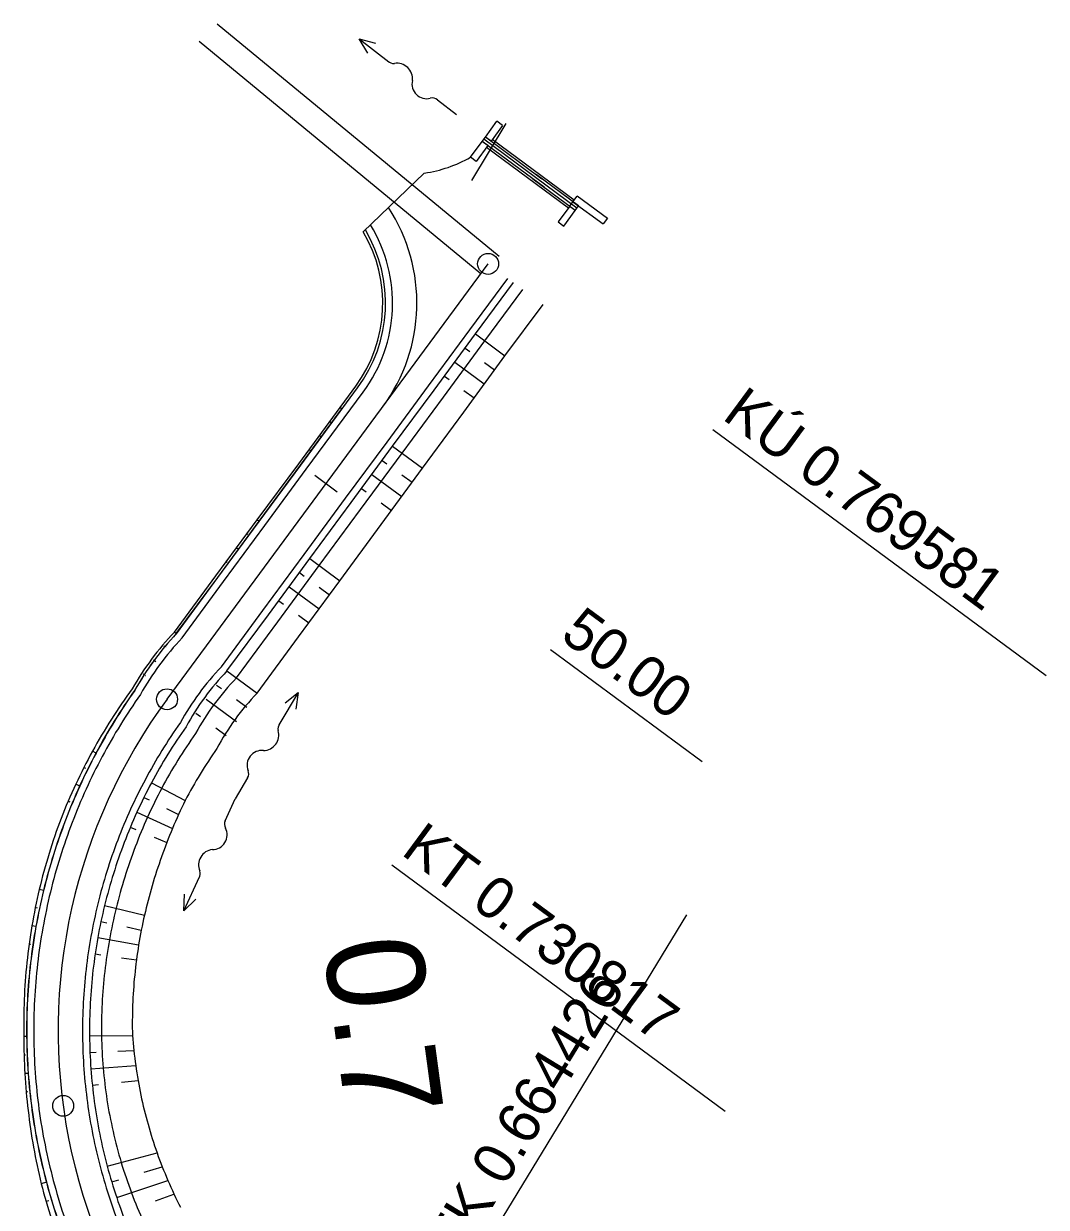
# Model space of a CAD drawing. Extents: x -481656 to -478728, y -1113199 to -1110710.
# Drawn here: x -479819.6 to -479746.4, y -1112732.9 to -1112648.1 of the extents above; entities that cross this region are included whole.
import ezdxf

# ---------------------------------------------------------------- set-up
doc = ezdxf.new("R2010")
doc.units = 0
for name, color, linetype in [('C1_HATCH_SLOPE_L', 7, 'Continuous'), ('C1_HATCH_SLOPE_R', 7, 'Continuous'), ('C1_HECTOMETRY', 7, 'Continuous'), ('C1_HLBODY', 7, 'Continuous'), ('C1_HRANA_TELESO', 7, 'Continuous'), ('C1_KORUNA', 7, 'Continuous'), ('C1_OSA', 7, 'Continuous'), ('C1_PRIKOP', 7, 'Continuous'), ('C1_STANICENI', 7, 'Continuous'), ('C1_VOZOVKA', 7, 'Continuous'), ('C1_ZPEVKRAJ', 7, 'Continuous'), ('DRENÁŽ', 7, 'Continuous'), ('křižovatky', 7, 'Continuous'), ('PLYN', 7, 'Continuous'), ('pomoc', 7, 'Continuous'), ('ŽLAB', 7, 'Continuous')]:
    doc.layers.add(name, color=color, linetype=linetype)

# ---------------------------------------------------------------- blocks, each defined once
blk = doc.blocks.new('A$C70B')
at = {"layer": 'DRENÁŽ'}
for p, q in [((0.869, 0.002), (-0.869, -0.002)), ((6.861, 0.426), (7.971, -0.002)), ((7.971, -0.002), (5.275, -0.002)), ((7.971, -0.002), (6.862, -0.478))]:
    blk.add_line(p, q, dxfattribs=at)
for centre, radius, start, end in [((0.872, 0.584), 0.582, 269.69241, 322.79009), ((2.168, -0.416), 1.055, 24.40393, 142.08362), ((4.08, 0.589), 1.109, 210.88731, 317.37071), ((5.319, -0.636), 0.636, 85.97658, 131.72478)]:
    blk.add_arc(centre, radius, start, end, dxfattribs=at)

msp = doc.modelspace()

# ---------------------------------------------------------------- linework, layer by layer
at = {"layer": 'C1_HATCH_SLOPE_L'}
for p, q in [((-479796.825, -1112675.729), (-479796.948, -1112675.638)), ((-479797.632, -1112676.686), (-479797.69, -1112676.644)), ((-479797.567, -1112676.735), (-479797.571, -1112676.732)), ((-479798.309, -1112677.741), (-479798.432, -1112677.65)), ((-479799.116, -1112678.698), (-479799.174, -1112678.656)), ((-479799.05, -1112678.747), (-479799.054, -1112678.744)), ((-479802.76, -1112683.778), (-479802.915, -1112683.663)), ((-479803.584, -1112684.724), (-479803.657, -1112684.669)), ((-479803.502, -1112684.784), (-479803.506, -1112684.781)), ((-479804.244, -1112685.79), (-479804.399, -1112685.675)), ((-479805.068, -1112686.736), (-479805.141, -1112686.681)), ((-479804.986, -1112686.796), (-479804.99, -1112686.793)), ((-479808.695, -1112691.826), (-479808.846, -1112691.715)), ((-479809.52, -1112692.771), (-479809.594, -1112692.716)), ((-479809.437, -1112692.832), (-479809.441, -1112692.829)), ((-479810.179, -1112693.838), (-479810.342, -1112693.717)), ((-479811.01, -1112694.778), (-479811.09, -1112694.719)), ((-479810.921, -1112694.844), (-479810.925, -1112694.841)), ((-479814.453, -1112700.385), (-479814.714, -1112700.245)), ((-479815.199, -1112701.488), (-479815.333, -1112701.422)), ((-479815.056, -1112701.559), (-479815.06, -1112701.557)), ((-479815.622, -1112702.752), (-479815.914, -1112702.619)), ((-479816.308, -1112703.896), (-479816.457, -1112703.833)), ((-479816.15, -1112703.962), (-479816.155, -1112703.96)), ((-479818.213, -1112710.226), (-479818.526, -1112710.149)), ((-479818.663, -1112711.48), (-479818.809, -1112711.449)), ((-479818.507, -1112711.513), (-479818.512, -1112711.512)), ((-479818.76, -1112712.808), (-479819.052, -1112712.756)), ((-479819.118, -1112714.09), (-479819.253, -1112714.07)), ((-479818.973, -1112714.111), (-479818.978, -1112714.11)), ((-479819.422, -1112720.691), (-479819.633, -1112720.693)), ((-479819.508, -1112722.016), (-479819.617, -1112722.02)), ((-479819.388, -1112722.011), (-479819.393, -1112722.011)), ((-479819.313, -1112723.329), (-479819.56, -1112723.347)), ((-479819.334, -1112724.658), (-479819.461, -1112724.672)), ((-479819.197, -1112724.644), (-479819.202, -1112724.644)), ((-479818.004, -1112731.13), (-479818.386, -1112731.232)), ((-479817.843, -1112732.46), (-479818.032, -1112732.517)), ((-479817.645, -1112732.401), (-479817.649, -1112732.402))]:
    msp.add_line(p, q, dxfattribs=at)
at = {"layer": 'C1_HATCH_SLOPE_R'}
for p, q in [((-479787.268, -1112670.352), (-479785.157, -1112671.909)), ((-479788.01, -1112671.358), (-479787.673, -1112671.606)), ((-479788.752, -1112672.364), (-479786.633, -1112673.926)), ((-479786.616, -1112672.386), (-479785.895, -1112672.918)), ((-479789.494, -1112673.37), (-479789.156, -1112673.618)), ((-479788.095, -1112674.401), (-479787.371, -1112674.935)), ((-479793.203, -1112678.4), (-479791.07, -1112679.973)), ((-479793.945, -1112679.406), (-479793.608, -1112679.654)), ((-479794.687, -1112680.412), (-479792.55, -1112681.988)), ((-479792.54, -1112680.442), (-479791.81, -1112680.981)), ((-479795.429, -1112681.418), (-479795.092, -1112681.666)), ((-479794.023, -1112682.455), (-479793.291, -1112682.995)), ((-479799.138, -1112686.448), (-479796.992, -1112688.031)), ((-479799.88, -1112687.454), (-479799.543, -1112687.703)), ((-479800.622, -1112688.46), (-479798.473, -1112690.045)), ((-479798.469, -1112688.495), (-479797.732, -1112689.038)), ((-479801.364, -1112689.466), (-479801.027, -1112689.715)), ((-479799.951, -1112690.508), (-479799.213, -1112691.052)), ((-479805.074, -1112694.497), (-479802.914, -1112696.089)), ((-479805.815, -1112695.503), (-479805.478, -1112695.752)), ((-479806.557, -1112696.509), (-479804.387, -1112698.109)), ((-479804.396, -1112696.55), (-479803.651, -1112697.099)), ((-479807.299, -1112697.515), (-479806.962, -1112697.764)), ((-479805.875, -1112698.566), (-479805.124, -1112699.119)), ((-479810.482, -1112702.502), (-479808.07, -1112703.789)), ((-479811.021, -1112703.552), (-479810.646, -1112703.736)), ((-479811.527, -1112704.617), (-479808.978, -1112705.779)), ((-479809.406, -1112704.349), (-479808.54, -1112704.777)), ((-479811.999, -1112705.698), (-479811.61, -1112705.861)), ((-479810.303, -1112706.408), (-479809.384, -1112706.792)), ((-479813.842, -1112711.295), (-479810.986, -1112711.994)), ((-479814.105, -1112712.445), (-479813.69, -1112712.533)), ((-479812.243, -1112712.84), (-479811.211, -1112713.058)), ((-479814.331, -1112713.603), (-479811.404, -1112714.128)), ((-479814.521, -1112714.767), (-479814.101, -1112714.829)), ((-479812.622, -1112715.047), (-479811.563, -1112715.203)), ((-479814.922, -1112720.646), (-479811.846, -1112720.615)), ((-479814.892, -1112721.825), (-479814.458, -1112721.807)), ((-479812.885, -1112721.742), (-479811.747, -1112721.695)), ((-479814.825, -1112723.003), (-479811.614, -1112722.77)), ((-479814.721, -1112724.178), (-479814.274, -1112724.132)), ((-479812.637, -1112723.961), (-479811.447, -1112723.837)), ((-479813.655, -1112729.973), (-479810.083, -1112729.023)), ((-479811.007, -1112730.41), (-479809.71, -1112730.022)), ((-479813.334, -1112731.108), (-479812.819, -1112730.954)), ((-479812.978, -1112732.233), (-479809.306, -1112731.006)), ((-479810.185, -1112732.458), (-479808.873, -1112731.974))]:
    msp.add_line(p, q, dxfattribs=at)
at = {"layer": 'C1_HECTOMETRY'}
msp.add_circle((-479816.81, -1112725.652), 0.75, dxfattribs=at)
at = {"layer": 'C1_HLBODY'}
for p, q in [((-479770.264, -1112677.2), (-479746.361, -1112694.828)), ((-479793.271, -1112708.398), (-479769.367, -1112726.025)), ((-479787.567, -1112737.356), (-479772.133, -1112711.981))]:
    msp.add_line(p, q, dxfattribs=at)
for centre in [(-479786.36, -1112665.33), (-479809.367, -1112696.527)]:
    msp.add_circle(centre, 0.75, dxfattribs=at)
at = {"layer": 'C1_HRANA_TELESO'}
for p, q in [((-479785.157, -1112671.909), (-479782.424, -1112668.234)), ((-479788.109, -1112675.944), (-479785.157, -1112671.909)), ((-479799.917, -1112679.662), (-479795.852, -1112674.1)), ((-479791.07, -1112679.973), (-479788.109, -1112675.944)), ((-479802.915, -1112683.663), (-479799.917, -1112679.662)), ((-479794.031, -1112684.002), (-479791.07, -1112679.973)), ((-479805.884, -1112687.687), (-479802.915, -1112683.663)), ((-479796.992, -1112688.031), (-479794.031, -1112684.002)), ((-479808.846, -1112691.715), (-479805.884, -1112687.687)), ((-479799.954, -1112692.06), (-479796.992, -1112688.031)), ((-479802.914, -1112696.089), (-479799.954, -1112692.06))]:
    msp.add_line(p, q, dxfattribs=at)
for centre, radius, start, end in [((-479793.441, -1112706.33), 21.234, 136.50563, 150.16536), ((-479777.505, -1112720.797), 42.508, 143.92415, 151.08689), ((-479790.322, -1112708.271), 17.52, 135.94864, 152.02132), ((-479777.336, -1112720.619), 42.571, 151.40625, 158.56852), ((-479777.072, -1112720.101), 35.029, 145.08335, 152.24543), ((-479776.743, -1112719.283), 34.949, 153.68312, 160.84848), ((-479777.12, -1112720.092), 42.583, 159.33516, 166.4972), ((-479777.005, -1112719.71), 34.845, 160.04478, 167.20775), ((-479777.104, -1112719.864), 42.546, 166.80102, 173.96332), ((-479777.085, -1112719.747), 34.776, 167.11831, 174.28111), ((-479777.152, -1112719.79), 42.49, 174.05545, 181.21788), ((-479777.15, -1112719.715), 34.708, 174.32379, 181.48668), ((-479777.136, -1112720.855), 42.497, 179.78211, 186.94476), ((-479777.416, -1112717.988), 34.53, 184.36389, 191.54165), ((-479777.797, -1112717.681), 34.22, 192.17183, 199.35546), ((-479777.009, -1112721.141), 42.589, 186.5414, 193.70493), ((-479778.169, -1112717.655), 33.879, 199.60558, 206.79196), ((-479777.083, -1112720.543), 42.663, 194.50961, 201.67174)]:
    msp.add_arc(centre, radius, start, end, dxfattribs=at)
at = {"layer": 'C1_KORUNA'}
for p, q in [((-479787.268, -1112670.352), (-479784.55, -1112666.666)), ((-479790.235, -1112674.376), (-479787.268, -1112670.352)), ((-479799.792, -1112679.753), (-479795.714, -1112674.223)), ((-479793.203, -1112678.4), (-479790.235, -1112674.376)), ((-479796.171, -1112682.424), (-479793.203, -1112678.4)), ((-479802.76, -1112683.778), (-479799.792, -1112679.753)), ((-479799.138, -1112686.448), (-479796.171, -1112682.424)), ((-479805.728, -1112687.802), (-479802.76, -1112683.778)), ((-479802.106, -1112690.472), (-479799.138, -1112686.448)), ((-479808.695, -1112691.826), (-479805.728, -1112687.802)), ((-479805.073, -1112694.497), (-479802.106, -1112690.472))]:
    msp.add_line(p, q, dxfattribs=at)
for centre, radius, start, end in [((-479793.287, -1112706.278), 21.125, 136.83359, 150.55201), ((-479791.463, -1112707.574), 18.875, 136.14304, 151.22455), ((-479777.174, -1112720.268), 42.25, 144.76332, 151.92529), ((-479777.174, -1112720.268), 37.75, 144.76331, 151.92528), ((-479777.174, -1112720.268), 42.25, 151.92529, 159.08726), ((-479777.174, -1112720.268), 37.75, 151.92528, 159.08726), ((-479777.174, -1112720.268), 42.25, 159.08726, 166.24924), ((-479777.174, -1112720.268), 37.75, 159.08726, 166.24923), ((-479777.174, -1112720.268), 42.25, 166.24924, 173.41121), ((-479777.174, -1112720.268), 37.75, 166.24923, 173.4112), ((-479777.174, -1112720.268), 42.25, 173.41121, 180.57318), ((-479777.174, -1112720.268), 37.75, 173.4112, 180.57317), ((-479777.174, -1112720.268), 42.25, 180.57318, 187.73515), ((-479777.174, -1112720.268), 37.75, 180.57317, 187.73514), ((-479777.174, -1112720.268), 42.25, 187.73515, 194.89713), ((-479777.174, -1112720.268), 37.75, 187.73514, 194.89712), ((-479777.174, -1112720.268), 37.75, 194.89712, 202.05909), ((-479777.174, -1112720.268), 42.25, 194.89713, 202.0591)]:
    msp.add_arc(centre, radius, start, end, dxfattribs=at)
at = {"layer": 'C1_OSA'}
msp.add_line((-479809.367, -1112696.527), (-479786.36, -1112665.33), dxfattribs=at)
msp.add_arc((-479777.174, -1112720.268), 40, 143.59269, 238.69063, dxfattribs=at)
at = {"layer": 'C1_PRIKOP'}
for p, q in [((-479786.594, -1112670.849), (-479783.875, -1112667.163)), ((-479789.561, -1112674.873), (-479786.594, -1112670.849)), ((-479792.529, -1112678.897), (-479789.561, -1112674.873)), ((-479799.8, -1112679.747), (-479796.833, -1112675.723)), ((-479795.497, -1112682.921), (-479792.529, -1112678.897)), ((-479802.768, -1112683.772), (-479799.8, -1112679.747)), ((-479798.464, -1112686.946), (-479795.497, -1112682.921)), ((-479805.736, -1112687.796), (-479802.768, -1112683.772)), ((-479801.432, -1112690.97), (-479798.464, -1112686.946)), ((-479808.703, -1112691.82), (-479805.736, -1112687.796)), ((-479804.399, -1112694.994), (-479801.432, -1112690.97))]:
    msp.add_line(p, q, dxfattribs=at)
for centre, radius, start, end in [((-479793.291, -1112706.275), 21.13, 136.83496, 150.55068), ((-479791.124, -1112707.815), 18.456, 135.99598, 151.36819), ((-479777.174, -1112720.268), 42.26, 144.76332, 151.92529), ((-479777.201, -1112720.312), 36.916, 144.68354, 151.84552), ((-479777.174, -1112720.268), 42.26, 151.92529, 159.08726), ((-479777.123, -1112720.156), 36.911, 152.11568, 159.27769), ((-479777.174, -1112720.268), 42.26, 159.08726, 166.24924), ((-479777.171, -1112720.259), 36.903, 159.10287, 166.26484), ((-479777.174, -1112720.268), 42.26, 166.24924, 173.41121), ((-479777.172, -1112720.259), 36.902, 166.26461, 173.42658), ((-479777.174, -1112720.268), 42.26, 173.41121, 180.57318), ((-479777.172, -1112720.218), 36.898, 173.48881, 180.65079), ((-479777.174, -1112720.268), 42.26, 180.57318, 187.73515), ((-479777.21, -1112719.81), 36.866, 181.28645, 188.44898), ((-479777.375, -1112719.329), 36.777, 189.2276, 196.39201), ((-479777.174, -1112720.268), 42.26, 187.73515, 194.89713), ((-479777.633, -1112718.977), 36.632, 197.03356, 204.20053), ((-479777.174, -1112720.268), 42.26, 194.89713, 202.0591)]:
    msp.add_arc(centre, radius, start, end, dxfattribs=at)
at = {"layer": 'C1_STANICENI'}
for p, q in [((-479797.177, -1112681.682), (-479798.786, -1112680.495)), ((-479781.885, -1112692.959), (-479771.02, -1112700.972))]:
    msp.add_line(p, q, dxfattribs=at)
at = {"layer": 'C1_VOZOVKA'}
for p, q in [((-479787.67, -1112670.055), (-479784.952, -1112666.369)), ((-479790.638, -1112674.079), (-479787.67, -1112670.055)), ((-479793.605, -1112678.103), (-479790.638, -1112674.079)), ((-479796.573, -1112682.127), (-479793.605, -1112678.103)), ((-479802.358, -1112684.074), (-479799.39, -1112680.05)), ((-479799.541, -1112686.152), (-479796.573, -1112682.127)), ((-479805.325, -1112688.098), (-479802.358, -1112684.074)), ((-479802.508, -1112690.176), (-479799.541, -1112686.152)), ((-479808.293, -1112692.122), (-479805.325, -1112688.098)), ((-479805.476, -1112694.2), (-479802.508, -1112690.176))]:
    msp.add_line(p, q, dxfattribs=at)
for centre, radius, start, end in [((-479793.084, -1112706.422), 20.875, 136.76418, 150.61946), ((-479791.666, -1112707.43), 19.125, 136.22776, 151.14187), ((-479777.174, -1112720.268), 41.75, 144.76332, 151.92529), ((-479777.174, -1112720.268), 38.25, 144.76331, 151.92528), ((-479777.174, -1112720.268), 41.75, 151.92529, 159.08726), ((-479777.174, -1112720.268), 38.25, 151.92528, 159.08726), ((-479777.174, -1112720.268), 41.75, 159.08726, 166.24924), ((-479777.174, -1112720.268), 38.25, 159.08726, 166.24923), ((-479777.174, -1112720.268), 41.75, 166.24924, 173.41121), ((-479777.174, -1112720.268), 38.25, 166.24923, 173.4112), ((-479777.174, -1112720.268), 41.75, 173.41121, 180.57318), ((-479777.174, -1112720.268), 38.25, 173.4112, 180.57317), ((-479777.174, -1112720.268), 41.75, 180.57318, 187.73515), ((-479777.174, -1112720.268), 38.25, 180.57317, 187.73514), ((-479777.174, -1112720.268), 41.75, 187.73515, 194.89713), ((-479777.174, -1112720.268), 38.25, 187.73514, 194.89712), ((-479777.174, -1112720.268), 38.25, 194.89712, 202.05909), ((-479777.174, -1112720.268), 41.75, 194.89713, 202.0591)]:
    msp.add_arc(centre, radius, start, end, dxfattribs=at)
at = {"layer": 'C1_ZPEVKRAJ'}
for p, q in [((-479787.67, -1112670.055), (-479784.952, -1112666.369)), ((-479790.638, -1112674.079), (-479787.67, -1112670.055)), ((-479793.605, -1112678.103), (-479790.638, -1112674.079)), ((-479799.39, -1112680.05), (-479795.311, -1112674.52)), ((-479796.573, -1112682.127), (-479793.605, -1112678.103)), ((-479802.358, -1112684.074), (-479799.39, -1112680.05)), ((-479799.541, -1112686.152), (-479796.573, -1112682.127)), ((-479805.325, -1112688.098), (-479802.358, -1112684.074)), ((-479802.508, -1112690.176), (-479799.541, -1112686.152)), ((-479808.293, -1112692.122), (-479805.325, -1112688.098)), ((-479805.476, -1112694.2), (-479802.508, -1112690.176))]:
    msp.add_line(p, q, dxfattribs=at)
for centre, radius, start, end in [((-479793.084, -1112706.422), 20.875, 136.76418, 150.61946), ((-479791.666, -1112707.43), 19.125, 136.22776, 151.14187), ((-479777.174, -1112720.268), 41.75, 144.76332, 151.92529), ((-479777.174, -1112720.268), 38.25, 144.76331, 151.92528), ((-479777.174, -1112720.268), 41.75, 151.92529, 159.08726), ((-479777.174, -1112720.268), 38.25, 151.92528, 159.08726), ((-479777.174, -1112720.268), 41.75, 159.08726, 166.24924), ((-479777.174, -1112720.268), 38.25, 159.08726, 166.24923), ((-479777.174, -1112720.268), 41.75, 166.24924, 173.41121), ((-479777.174, -1112720.268), 38.25, 166.24923, 173.4112), ((-479777.174, -1112720.268), 41.75, 173.41121, 180.57318), ((-479777.174, -1112720.268), 38.25, 173.4112, 180.57317), ((-479777.174, -1112720.268), 41.75, 180.57318, 187.73515), ((-479777.174, -1112720.268), 38.25, 180.57317, 187.73514), ((-479777.174, -1112720.268), 41.75, 187.73515, 194.89713), ((-479777.174, -1112720.268), 38.25, 187.73514, 194.89712), ((-479777.174, -1112720.268), 38.25, 194.89712, 202.05909), ((-479777.174, -1112720.268), 41.75, 194.89713, 202.0591)]:
    msp.add_arc(centre, radius, start, end, dxfattribs=at)
at = {"layer": 'křižovatky'}
msp.add_line((-479795.305, -1112663.043), (-479790.933, -1112658.823), dxfattribs=at)
for centre, radius, start, end in [((-479792.206, -1112649.726), 9.185, 277.97005, 299.91517), ((-479803.963, -1112668.139), 10.75, 323.59269, 31.37909), ((-479803.993, -1112668.156), 10.081, 323.86732, 30.47383), ((-479803.963, -1112668.139), 10.25, 323.59269, 30.75296)]:
    msp.add_arc(centre, radius, start, end, dxfattribs=at)
at = {"layer": 'pomoc'}
for p, q in [((-479805.765, -1112648.12), (-479785.577, -1112664.776)), ((-479807.065, -1112649.375), (-479786.877, -1112666.031)), ((-479787.52, -1112659.35), (-479785.056, -1112655.265))]:
    msp.add_line(p, q, dxfattribs=at)
msp.add_arc((-479803.963, -1112668.139), 12.5, 323.59269, 33.16788, dxfattribs=at)
at = {"layer": 'ŽLAB'}
for p, q in [((-479786.557, -1112656.24), (-479785.725, -1112655.113)), ((-479785.323, -1112655.41), (-479786.154, -1112656.537)), ((-479785.323, -1112655.41), (-479785.725, -1112655.113)), ((-479787.626, -1112657.688), (-479786.794, -1112656.561)), ((-479786.794, -1112656.561), (-479786.557, -1112656.24)), ((-479782.348, -1112659.845), (-479786.794, -1112656.561)), ((-479786.392, -1112656.858), (-479786.794, -1112656.561)), ((-479779.995, -1112661.333), (-479786.675, -1112656.4)), ((-479786.557, -1112656.239), (-479782.512, -1112659.226)), ((-479786.154, -1112656.537), (-479786.557, -1112656.24)), ((-479780.19, -1112660.754), (-479786.065, -1112656.416)), ((-479786.392, -1112656.858), (-479787.224, -1112657.985)), ((-479786.481, -1112656.979), (-479780.606, -1112661.318)), ((-479787.224, -1112657.985), (-479787.626, -1112657.688)), ((-479779.877, -1112661.172), (-479782.914, -1112658.929)), ((-479780.114, -1112661.494), (-479783.152, -1112659.251)), ((-479780.279, -1112660.875), (-479779.983, -1112660.472)), ((-479777.811, -1112662.067), (-479779.983, -1112660.472)), ((-479780.517, -1112661.197), (-479781.348, -1112662.323)), ((-479780.946, -1112662.62), (-479780.114, -1112661.494)), ((-479780.517, -1112661.197), (-479780.279, -1112660.875)), ((-479780.279, -1112660.875), (-479778.11, -1112662.468)), ((-479780.114, -1112661.494), (-479779.877, -1112661.172)), ((-479781.348, -1112662.323), (-479780.946, -1112662.62)), ((-479777.814, -1112662.065), (-479778.11, -1112662.468))]:
    msp.add_line(p, q, dxfattribs=at)

# ---------------------------------------------------------------- block references
at = {"layer": 'PLYN'}
for p, rotation in [((-479789.305, -1112654.098), 142.2083198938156), ((-479804.038, -1112702.9), 59.384220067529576), ((-479804.839, -1112704.44), -114.58073141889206)]:
    msp.add_blockref('A$C70B', p, dxfattribs=dict(at, rotation=rotation))

# ---------------------------------------------------------------- texts
at = {"layer": 'C1_HECTOMETRY'}
msp.add_text('0.7', height=7, rotation=277.68952, dxfattribs=at).set_placement((-479798.202, -1112714))
at = {"layer": 'C1_HLBODY'}
for s, height, rotation, p in [('KÚ 0.769581', 2.999, 323.5927, (-479769.671, -1112676.395)), ('KT 0.730817', 2.999, 323.5927, (-479792.678, -1112707.593)), ('TK 0.664426', 3, 58.69064, (-479788.422, -1112736.837))]:
    msp.add_text(s, height=height, rotation=rotation, dxfattribs=at).set_placement(p)
at = {"layer": 'C1_STANICENI'}
msp.add_text('50.00', height=2.999, rotation=323.5927, dxfattribs=at).set_placement((-479781.292, -1112692.154))

doc.saveas('drawing.dxf')
